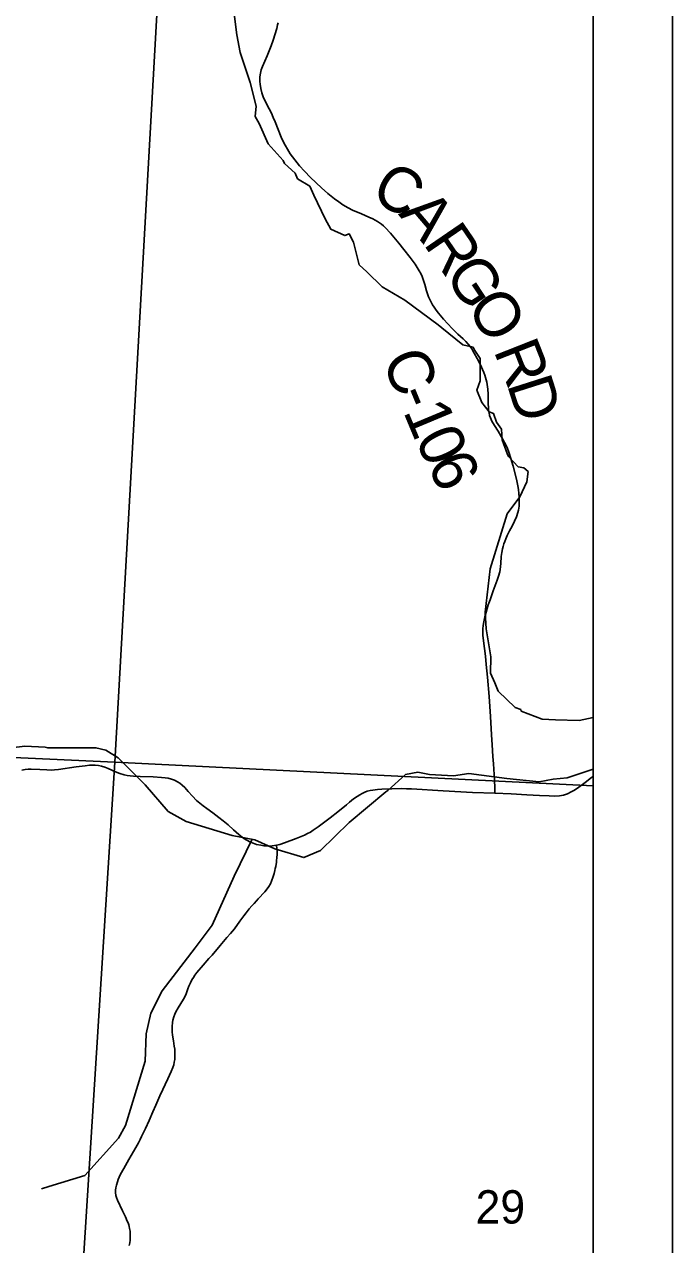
# Model space of a CAD drawing. Extents: x 0 to 34, y 0 to 22.
# Drawn here: x 8.185 to 9, y 17.604 to 19.136 of the extents above; entities that cross this region are included whole.
import ezdxf

# ---------------------------------------------------------------- set-up
doc = ezdxf.new("R2010")
doc.units = 0
for name, color, linetype in [('Default', 7, 'Continuous'), ('GM_X_County_Road', 7, 'Continuous'), ('GM_X_County_Road_Text', 7, 'Continuous'), ('GM_X_Minor_River', 7, 'Continuous'), ('GM_X_Section', 7, 'Continuous'), ('GM_X_Section_Text', 7, 'Continuous'), ('SH_Cut_Line', 7, 'Continuous'), ('SH_Data', 7, 'Continuous')]:
    doc.layers.add(name, color=color, linetype=linetype)

msp = doc.modelspace()

# ---------------------------------------------------------------- linework, layer by layer
at = {"layer": 'Default'}
msp.add_lwpolyline([(8.9, 14.1), (8.9, 19.1797), (8.8731, 19.181), (8.4872, 19.2008), (7.1944, 19.2649), (6.2536, 19.3066), (6.2282, 18.9116), (6.1917, 18.3385), (6.1723, 18.0255), (6.1151, 17.0743), (6.0901, 16.6706), (6.0633, 16.2368)], dxfattribs=at)
for points in [[(8.9, 18.1799), (8.9, 19.1878), (8.3558, 19.2156), (8.299, 18.2095)], [(8.9, 17.1336), (8.9, 18.1799), (8.299, 18.2095), (8.2333, 17.168)]]:
    msp.add_lwpolyline(points, close=True, dxfattribs=at)
at = {"layer": 'GM_X_County_Road'}
for points in [[(8.6089, 18.8977), (8.5978, 18.9025), (8.5921, 18.9055), (8.5858, 18.9092), (8.5806, 18.9128), (8.5751, 18.9168), (8.5669, 18.9235), (8.5586, 18.9305), (8.5451, 18.9433), (8.5373, 18.9513), (8.5311, 18.9583), (8.5252, 18.9655), (8.5196, 18.973), (8.5159, 18.979), (8.5131, 18.9839), (8.5106, 18.9886), (8.5079, 18.9943), (8.5004, 19.0132), (8.4981, 19.0186), (8.4958, 19.0241), (8.4931, 19.0295), (8.4881, 19.0391), (8.4856, 19.0448), (8.484, 19.0496), (8.4827, 19.0551), (8.4818, 19.0606), (8.4815, 19.0639), (8.4814, 19.0668), (8.4815, 19.0699), (8.4821, 19.0743), (8.4831, 19.0786), (8.4846, 19.0827), (8.4877, 19.0896), (8.4906, 19.0961), (8.4931, 19.1023), (8.4955, 19.1087), (8.498, 19.1157), (8.5025, 19.1305), (8.5037, 19.135), (8.5042, 19.1376)], [(8.6941, 18.792), (8.6934, 18.7938), (8.6907, 18.8013), (8.6885, 18.809), (8.687, 18.8142), (8.6853, 18.819), (8.6837, 18.8228), (8.6817, 18.8265), (8.6792, 18.8305), (8.6765, 18.8347), (8.67, 18.8432), (8.6623, 18.853), (8.6559, 18.8611), (8.6456, 18.8735), (8.6389, 18.8808), (8.6365, 18.8829), (8.6342, 18.8848), (8.6317, 18.8866), (8.6291, 18.8883), (8.6263, 18.8898), (8.6231, 18.8914), (8.6181, 18.8937), (8.6089, 18.8977)], [(8.7766, 18.1704), (8.7764, 18.1768), (8.776, 18.1873), (8.7748, 18.2072), (8.7742, 18.2165), (8.7733, 18.2314), (8.7725, 18.2438), (8.7711, 18.2667), (8.7694, 18.2921), (8.7674, 18.3163), (8.7659, 18.3322), (8.7648, 18.3424), (8.7623, 18.3616), (8.7616, 18.3691), (8.7615, 18.3734), (8.7616, 18.3773), (8.7619, 18.3805), (8.7622, 18.3834), (8.763, 18.3877), (8.764, 18.3919), (8.7657, 18.3979), (8.7684, 18.4068), (8.7706, 18.4133), (8.7747, 18.4244), (8.7797, 18.4378), (8.7814, 18.4431), (8.7827, 18.4484), (8.7833, 18.4515), (8.7837, 18.4549), (8.7841, 18.4589), (8.7847, 18.4675), (8.7854, 18.4725), (8.7864, 18.4774), (8.7871, 18.4802), (8.788, 18.4834), (8.7891, 18.4866), (8.7904, 18.49), (8.7921, 18.494), (8.7951, 18.4998), (8.7983, 18.5059), (8.8014, 18.512), (8.8038, 18.5174), (8.8056, 18.523), (8.8062, 18.5257), (8.8067, 18.5283), (8.8071, 18.531), (8.8072, 18.5335), (8.8073, 18.5378), (8.8072, 18.5421), (8.8069, 18.5469), (8.8063, 18.5516), (8.8056, 18.5564), (8.8039, 18.5647), (8.7997, 18.5809), (8.7969, 18.5906), (8.7943, 18.5987), (8.7926, 18.6031), (8.7909, 18.607), (8.7888, 18.6109), (8.7861, 18.6155), (8.7806, 18.6252), (8.7761, 18.6322), (8.7729, 18.6376), (8.7711, 18.6416), (8.7701, 18.6446), (8.7693, 18.6483), (8.7688, 18.6511), (8.7686, 18.6539), (8.7684, 18.6601), (8.7683, 18.6715), (8.7678, 18.6778), (8.7671, 18.6835), (8.7664, 18.6867), (8.7657, 18.6895), (8.7649, 18.6925), (8.764, 18.6955), (8.7627, 18.6987), (8.7613, 18.7023), (8.7584, 18.7084), (8.7545, 18.7161), (8.7508, 18.7231), (8.7477, 18.7283), (8.7456, 18.7314), (8.7432, 18.7344), (8.7403, 18.7375), (8.7366, 18.7411), (8.7302, 18.7469), (8.7265, 18.7504), (8.723, 18.7539), (8.7174, 18.7597), (8.712, 18.7658), (8.7056, 18.7731), (8.7027, 18.7769), (8.7002, 18.7808), (8.6982, 18.7838), (8.6965, 18.7868), (8.6948, 18.7903), (8.6941, 18.792)], [(8.1824, 18.1995), (8.1863, 18.2002), (8.1901, 18.2005), (8.1941, 18.2007), (8.2049, 18.2002), (8.2135, 18.1998), (8.2191, 18.1996), (8.2234, 18.1999), (8.2283, 18.2004), (8.2506, 18.2035), (8.2619, 18.205), (8.2674, 18.2055), (8.2708, 18.2057), (8.2744, 18.2056), (8.2786, 18.2051), (8.2823, 18.2043), (8.2865, 18.203), (8.2906, 18.2014), (8.3, 18.1972), (8.3054, 18.1952), (8.3108, 18.1937), (8.3147, 18.1928), (8.3184, 18.1922), (8.3227, 18.1918), (8.3308, 18.1914), (8.3474, 18.191), (8.3579, 18.1904), (8.3623, 18.1899), (8.3663, 18.1892), (8.3703, 18.1882), (8.3742, 18.1867), (8.3779, 18.1848), (8.3807, 18.183), (8.3838, 18.1806), (8.3869, 18.1776), (8.3913, 18.1726), (8.3965, 18.1666), (8.4017, 18.1614), (8.4057, 18.158), (8.41, 18.1547), (8.4147, 18.1513), (8.4223, 18.1459), (8.4298, 18.1402), (8.4352, 18.136), (8.4415, 18.1307), (8.448, 18.1247), (8.4548, 18.1187), (8.4613, 18.1137), (8.4649, 18.1114), (8.4688, 18.1093), (8.4729, 18.1076), (8.4772, 18.1063), (8.4827, 18.1051), (8.4864, 18.1046), (8.4891, 18.1043), (8.4926, 18.1042), (8.497, 18.1045), (8.5023, 18.1053), (8.5063, 18.1063), (8.5125, 18.1083), (8.5271, 18.1136), (8.5374, 18.1179), (8.5414, 18.1198), (8.5449, 18.1217), (8.5484, 18.1239), (8.5545, 18.1282), (8.5696, 18.1396), (8.5794, 18.1473), (8.5901, 18.1559), (8.5941, 18.1594), (8.5992, 18.1634), (8.6034, 18.1664), (8.6068, 18.1684), (8.61, 18.1703), (8.6133, 18.1718), (8.6162, 18.1729), (8.6198, 18.1738), (8.6235, 18.1745), (8.6291, 18.1751), (8.6348, 18.1754), (8.6471, 18.176), (8.6593, 18.1762), (8.6656, 18.1761), (8.6717, 18.1758), (8.7115, 18.1733), (8.7487, 18.1714), (8.7766, 18.1704), (8.7971, 18.1695), (8.817, 18.1685), (8.8329, 18.1676), (8.8448, 18.167), (8.8521, 18.1669), (8.8578, 18.1673), (8.8628, 18.1682), (8.8678, 18.1699), (8.8726, 18.1722), (8.8768, 18.1745), (8.8822, 18.1782), (8.8899, 18.1839), (8.8982, 18.1902), (8.9, 18.1915)], [(8.3173, 17.6027), (8.3178, 17.606), (8.3182, 17.6094), (8.3185, 17.6136), (8.3185, 17.6178), (8.3182, 17.6206), (8.3176, 17.6241), (8.3171, 17.6264), (8.3166, 17.6285), (8.3157, 17.631), (8.3147, 17.6332), (8.3123, 17.6387), (8.3086, 17.6462), (8.3024, 17.6594), (8.301, 17.6631), (8.3003, 17.6655), (8.2999, 17.669), (8.3001, 17.6721), (8.3004, 17.675), (8.301, 17.6783), (8.3024, 17.6828), (8.3032, 17.6856), (8.3044, 17.6886), (8.3063, 17.6924), (8.3104, 17.6994), (8.3167, 17.7105), (8.3198, 17.7157), (8.3255, 17.7255), (8.3288, 17.7315), (8.3309, 17.7356), (8.3328, 17.7395), (8.3375, 17.7497), (8.3421, 17.7597), (8.3468, 17.7703), (8.3507, 17.779), (8.3557, 17.7906), (8.3592, 17.7984), (8.3623, 17.8049), (8.3655, 17.8117), (8.3697, 17.8211), (8.3719, 17.8262), (8.3731, 17.8296), (8.3738, 17.8327), (8.3743, 17.836), (8.3745, 17.8397), (8.3745, 17.8439), (8.3743, 17.8493), (8.3738, 17.853), (8.3727, 17.8597), (8.3717, 17.8668), (8.3713, 17.8711), (8.3711, 17.8749), (8.3711, 17.8778), (8.3715, 17.8826), (8.3719, 17.8854), (8.3731, 17.8898), (8.3744, 17.8932), (8.3757, 17.896), (8.3787, 17.9012), (8.3819, 17.9065), (8.3854, 17.9121), (8.3869, 17.9147), (8.3886, 17.9185), (8.3897, 17.9212), (8.3909, 17.9248), (8.3922, 17.9283), (8.3932, 17.9306), (8.394, 17.9326), (8.3957, 17.9361), (8.3978, 17.9393), (8.3996, 17.942), (8.4022, 17.9454), (8.4101, 17.9548), (8.4173, 17.9628), (8.4213, 17.9673), (8.4313, 17.9794), (8.4399, 17.9892), (8.4446, 17.9942), (8.4494, 18.0001), (8.4563, 18.0097), (8.4613, 18.0166), (8.464, 18.0201), (8.4681, 18.0254), (8.4714, 18.0293), (8.4742, 18.0322), (8.4771, 18.0354), (8.4794, 18.0377), (8.4875, 18.0467), (8.4906, 18.0503), (8.4928, 18.0535), (8.4945, 18.0567), (8.496, 18.0601), (8.498, 18.0659), (8.4992, 18.0696), (8.5002, 18.0736), (8.5007, 18.0759), (8.5012, 18.0786), (8.5018, 18.0816), (8.5021, 18.0835), (8.5024, 18.0862), (8.5027, 18.0893), (8.503, 18.0939), (8.5029, 18.0975), (8.5027, 18.1007), (8.5023, 18.1053)]]:
    msp.add_lwpolyline(points, dxfattribs=at)
at = {"layer": 'GM_X_Minor_River'}
for points in [[(8.9, 18.2656), (8.8824, 18.2616), (8.8529, 18.2626), (8.8359, 18.2633), (8.8098, 18.2735), (8.8091, 18.2754), (8.8023, 18.2781), (8.7807, 18.2986), (8.7765, 18.3092), (8.7712, 18.321), (8.7716, 18.3419), (8.7659, 18.3768), (8.7644, 18.3977), (8.7707, 18.4521), (8.7922, 18.5213), (8.8081, 18.5426), (8.8168, 18.5613), (8.8183, 18.5742), (8.813, 18.5791), (8.8061, 18.5803), (8.7937, 18.5932), (8.7921, 18.5969), (8.7857, 18.614), (8.7849, 18.6277), (8.7789, 18.6364), (8.7751, 18.6471), (8.7694, 18.6493), (8.7603, 18.6611), (8.7539, 18.6763), (8.758, 18.6881), (8.758, 18.7162), (8.7516, 18.7261), (8.7493, 18.7303), (8.7364, 18.7333), (8.71, 18.7549), (8.7054, 18.7587), (8.6634, 18.7893), (8.6351, 18.8064), (8.6158, 18.825), (8.6063, 18.8337), (8.5991, 18.8622), (8.5934, 18.8728), (8.5881, 18.8705), (8.5704, 18.8785), (8.5632, 18.8914), (8.5491, 18.9214), (8.5442, 18.9324), (8.5287, 18.9418), (8.5257, 18.949), (8.5124, 18.9612), (8.5106, 18.965), (8.4916, 18.9858), (8.4803, 19.0113), (8.4753, 19.02), (8.4765, 19.0329), (8.4693, 19.0626), (8.4564, 19.1002), (8.4526, 19.1226), (8.4488, 19.1522)], [(8.9, 18.2007), (8.8674, 18.1897), (8.85, 18.1881), (8.8322, 18.1847), (8.7918, 18.1891), (8.7441, 18.1951), (8.7245, 18.1924), (8.6946, 18.1938), (8.6799, 18.1968), (8.6644, 18.1938), (8.6421, 18.174), (8.6398, 18.1724), (8.5934, 18.1339), (8.5575, 18.0985), (8.5367, 18.0897), (8.5, 18.1007), (8.4751, 18.112), (8.4467, 18.1173), (8.3889, 18.135), (8.3662, 18.1475), (8.337, 18.1812), (8.3033, 18.215), (8.2878, 18.2244), (8.2754, 18.2275), (8.2149, 18.2273), (8.2115, 18.2281), (8.1858, 18.2295), (8.148, 18.2249)], [(8.4716, 18.1126), (8.4492, 18.0665), (8.4212, 18.0047), (8.3999, 17.9765), (8.3586, 17.9224), (8.3445, 17.8944), (8.3385, 17.8684), (8.3374, 17.8342), (8.3123, 17.7534), (8.3035, 17.7373), (8.2616, 17.6905), (8.2162, 17.6767), (8.207, 17.6736)]]:
    msp.add_lwpolyline(points, dxfattribs=at)
at = {"layer": 'GM_X_Section'}
for points in [[(8.3558, 19.2156), (8.299, 18.2095), (7.2546, 18.2574), (7.3152, 19.2658)], [(8.299, 18.2095), (8.2333, 17.168), (7.1862, 17.219), (7.2546, 18.2574)]]:
    msp.add_lwpolyline(points, close=True, dxfattribs=at)
at = {"layer": 'SH_Cut_Line'}
msp.add_lwpolyline([(8.9, 14.1), (8.9, 20.9), (2.1, 20.9), (2.1, 14.1)], dxfattribs=at)
at = {"layer": 'SH_Data'}
for p, q in [((9, 21), (9, 14)), ((8.9, 20.9), (8.9, 14.1))]:
    msp.add_line(p, q, dxfattribs=at)

# ---------------------------------------------------------------- texts
at = {"layer": 'GM_X_County_Road_Text'}
for s, rotation, p in [('C', 329.1581, (8.6182, 18.9183)), ('A', 310.3338, (8.6545, 18.8975)), ('R', 304.3959, (8.6859, 18.8606)), ('G', 303.4335, (8.7121, 18.8223)), ('O', 303.194, (8.7397, 18.7807)), ('R', 291.5072, (8.7746, 18.7265)), ('C', 292.4711, (8.6341, 18.7149)), ('D', 287.6504, (8.7914, 18.6841)), ('-', 292.5162, (8.652, 18.6717)), ('1', 292.6769, (8.661, 18.65)), ('0', 295.4696, (8.6757, 18.615)), ('6', 295.758, (8.6909, 18.5831))]:
    msp.add_text(s, height=0.0568, rotation=rotation, dxfattribs=at).set_placement(p)
at = {"layer": 'GM_X_Section_Text'}
msp.add_text('29', height=0.04186, rotation=0, dxfattribs=at).set_placement((8.7524, 17.6302))

doc.saveas('drawing.dxf')
